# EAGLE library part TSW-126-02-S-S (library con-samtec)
THROUGH-HOLE .025" SQ POST HEADER Source: Samtec TSW.pdf
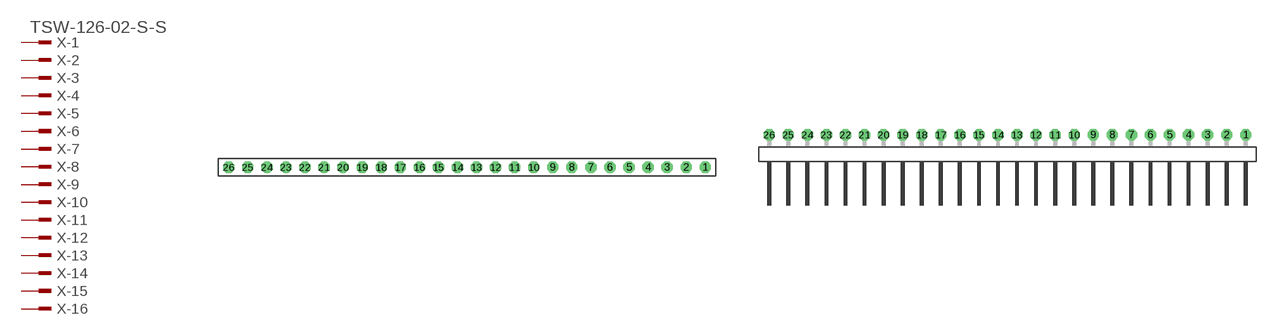
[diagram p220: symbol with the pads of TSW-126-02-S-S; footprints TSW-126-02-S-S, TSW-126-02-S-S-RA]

Designator prefix X; gates -1=MPINV -2=MPIN -3=MPIN -4=MPIN -5=MPIN -6=MPIN -7=MPIN -8=MPIN -9=MPIN -10=MPIN -11=MPIN -12=MPIN -13=MPIN -14=MPIN -15=MPIN -16=MPIN -17=MPIN -18=MPIN -19=MPIN -20=MPIN -21=MPIN -22=MPIN -23=MPIN -24=MPIN -25=MPIN -26=MPIN

## TSW-126-02-S-S (OC_FARNELL: unknown; OC_NEWARK: unknown)  [TSW-126-02-S-S]
1  -1:1  pas
2  -2:1  pas
3  -3:1  pas
4  -4:1  pas
5  -5:1  pas
6  -6:1  pas
7  -7:1  pas
8  -8:1  pas
9  -9:1  pas
10  -10:1  pas
11  -11:1  pas
12  -12:1  pas
13  -13:1  pas
14  -14:1  pas
15  -15:1  pas
16  -16:1  pas
17  -17:1  pas
18  -18:1  pas
19  -19:1  pas
20  -20:1  pas
21  -21:1  pas
22  -22:1  pas
23  -23:1  pas
24  -24:1  pas
25  -25:1  pas
26  -26:1  pas

## TSW-126-02-S-S-RA (OC_FARNELL: unknown; OC_NEWARK: unknown)  [TSW-126-02-S-S-RA]
Pads as for TSW-126-02-S-S

## Footprint TSW-126-02-S-S (pad centres in mm)
THROUGH-HOLE .025" SQ POST HEADER Source: Samtec TSW.pdf
drill 1 pad 1.5 octagon: 1 31.75,0; 2 29.21,0; 3 26.67,0; 4 24.13,0; 5 21.59,0; 6 19.05,0; 7 16.51,0; 8 13.97,0; 9 11.43,0; 10 8.89,0; 11 6.35,0; 12 3.81,0; 13 1.27,0; 14 -1.27,0; 15 -3.81,0; 16 -6.35,0; 17 -8.89,0; 18 -11.43,0; 19 -13.97,0; 20 -16.51,0; 21 -19.05,0; 22 -21.59,0; 23 -24.13,0; 24 -26.67,0; 25 -29.21,0; 26 -31.75,0

## Footprint TSW-126-02-S-S-RA (pad centres in mm)
THROUGH-HOLE .025" SQ POST HEADER Source: Samtec TSW.pdf
drill 1 pad 1.5 octagon: 1 31.75,1.524; 2 29.21,1.524; 3 26.67,1.524; 4 24.13,1.524; 5 21.59,1.524; 6 19.05,1.524; 7 16.51,1.524; 8 13.97,1.524; 9 11.43,1.524; 10 8.89,1.524; 11 6.35,1.524; 12 3.81,1.524; 13 1.27,1.524; 14 -1.27,1.524; 15 -3.81,1.524; 16 -6.35,1.524; 17 -8.89,1.524; 18 -11.43,1.524; 19 -13.97,1.524; 20 -16.51,1.524; 21 -19.05,1.524; 22 -21.59,1.524; 23 -24.13,1.524; 24 -26.67,1.524; 25 -29.21,1.524; 26 -31.75,1.524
